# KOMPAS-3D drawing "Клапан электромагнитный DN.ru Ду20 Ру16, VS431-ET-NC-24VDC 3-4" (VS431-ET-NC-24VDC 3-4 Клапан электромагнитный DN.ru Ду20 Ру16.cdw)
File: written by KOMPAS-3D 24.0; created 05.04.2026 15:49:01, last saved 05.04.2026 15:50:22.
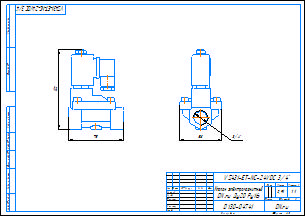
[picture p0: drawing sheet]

Document properties: c3d_UniqueCompID: ef56311e-7521-43dc-8291-0e6108b3d81d; Автор: artio; Класс точности: c; Знак неуказанной шероховатости: Шероховатость не задана; Рассекать на разрезах: Да; Автор: artio; Форматы листов документа: A3; Полное имя файла: VS431-ET-NC-24VDC 3-4 Клапан электромагнитный DN.ru Ду20 Ру16.m3d; Масса: 0.907; Наименование: Клапан электромагнитный DN.ru Ду20 Ру16; Количество листов документа: 1; Примечание: D130-04741

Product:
- Body: Тело 1  | qty 1
    Масса: 1.198355
- Part/product: Клапан электромагнитный DN.ru Ду20 Ру16  | designation VS431-ET-NC-24VDC 3-4
    Масса: 0.907
    Раздел спецификации: Прочие изделия
    Форматы листов документа: A3
    Примечание: D130-04741
    additional columns: ef56311e-7521-43dc-8291-0e6108b3d81d; artio; c; Шероховатость не задана; Да

Views: Вид 1, Спереди, Проекционный вид 2
Referenced files in C:\Users\artio\OneDrive\Рабочий стол\Клапан электромагнитный DN.ru\VS431\VS431-ET-NC\: VS431-ET-NC-24VDC 3-4 Клапан электромагнитный DN.ru Ду20 Ру16.m3d
Referenced files in C:\Users\artio\OneDrive\Рабочий стол\Клапан электромагнитный DN.ru\VS431\VS431-ET-NC\VS431-ET-NC-24VDC\Ду20\: VS431-ET-NC-24VDC 3-4 Клапан электромагнитный DN.ru Ду20 Ру16.cdw, VS431-ET-NC-24VDC 3-4 Клапан электромагнитный DN.ru Ду20 Ру16.m3d
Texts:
  VS431-ET-NC-24VDC 3-4
  Клапан электромагнитный
  DN.ru Ду20 Ру16
  VS431-ET-NC-24VDC 3/4"
  VS431-ET-NC-24VDC 3/4"-
  Клапан электромагнитный DN.ru Ду20 Ру16
  VS431-ET-NC-24VDC 3-4 Клапан электромагнитный DN.ru Ду20 Ру16
Dimensions and other numbers on the sheet: 0; 3; 2; 4; 58; 3/4"; 75; 110; 1:1; 1; 0,91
